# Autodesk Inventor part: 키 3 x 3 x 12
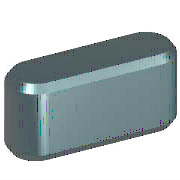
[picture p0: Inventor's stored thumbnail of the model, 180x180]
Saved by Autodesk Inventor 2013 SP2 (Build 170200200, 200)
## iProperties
Created: 2012-02
Part Number: 키 3 x 3 x 12
Material: 강철, 연강
Description: 키 및 해당 키홈
Document SubType Name: Modeling
Standard: KS B 1311
Designer: mduedu
Standards Organization: KS
Language: ko-KR
Size Designation: 3 x 3 x 12
Categories: <MemberInstance><Categories><Category DisplayName="샤프트 부품" InternalName="7f7aeb1f-a693-4053-b835-cee3144e0d98" Mnemonic="SHFT"><Category DisplayName="키" Interna
Density: 1 g/cm^3
IsCustomPart: 1
Author: mduedu
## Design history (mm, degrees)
workplane "Work Plane1"
workplane "Work Plane2"
sketch "스케치1"
  geometry: L1 (1.5, 1.5)-(10.5, 1.5); L2 (10.5, -1.5)-(1.5, -1.5); L3 (0, 9.4)-(0, -7.4) reference; L4 (-5, 0)-(30, 0) reference; L5 (12, 0)-(12, 7); A1 r 1.5 centre (1.5, 0) between (1.5, 1.5) and (1.5, -1.5); A2 r 1.5 centre (10.5, 0) between (10.5, -1.5) and (10.5, 1.5)
  constraints: 6 end point, 5 point on circle, 4 tangent, 3 point on line, 2 centre point, 1 horizontal, 1 parallel, 1 perpendicular
  dimensions: "d0" = 1.5 radius of A1 (= 0.5 x PB); "d13" = 1.5 radius of A2 (= 0.5 x PB); "d14" = 12 distance between parallel lines of L5 L3 (= NLG)
extrude "본체1" new body sketch "스케치1" taper "d3" = 0 deg; stored distance "d4" = 10
workplane "Work Plane3"
body "Solid1"
chamfer "모따기1" distance "d8" = 0.25 (= PHH); stored, may be unused: second distance "d9" = 0.25 (= PHH), angle "d15" = 45 deg
other parameters: "d1" = -1.8 (= -PNT), "d2" = 1.2 (= PH - PNT), "NLG" = 12 [user parameter; used in 3 equation terms], "PB" = 3 [user parameter; used in 2 equation terms], "PNT" = 1.8 [user parameter; used in 2 equation terms], "PH" = 3 [user parameter; used in 1 equation term], "PHH" = 0.25 [user parameter; used in 2 equation terms], "d10" = 0, "d16" = 0, "d17" = 0, "d18" = 0, "WDMIN" = 8 [user parameter], "PLB2" = 12 (= NLG) [user parameter], "PLB1" = 12 (= NLG) [user parameter], "RR" = 0.08 [user parameter], "PUEB" = 1.4 [user parameter]
